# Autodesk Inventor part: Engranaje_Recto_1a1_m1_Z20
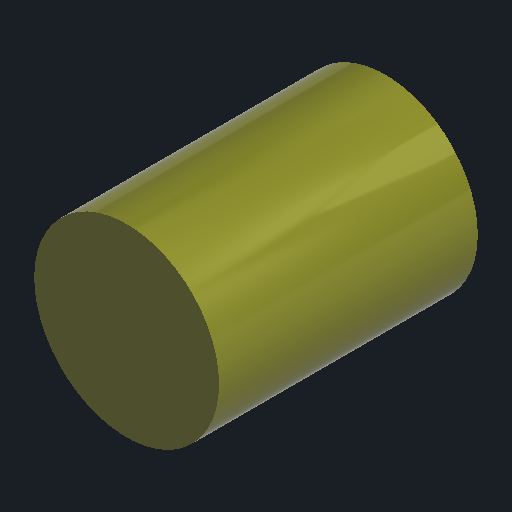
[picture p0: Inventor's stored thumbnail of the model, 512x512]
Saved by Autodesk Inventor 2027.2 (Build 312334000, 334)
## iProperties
Part Number: Engranaje_Recto_1a1_m1_Z20
Material: Genérico
Document SubType Name: Modelado
Designer: Usuario
Appearance: Por defecto
Author: Usuario
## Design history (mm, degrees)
sketch "Boceto1"
  geometry: L1 (8.702, -0.915)-(10.985, -0.576); L2 (10.985, -0.576)-(10.985, 0.576); L3 (10.985, 0.576)-(8.702, 0.915); L4 (8.702, 0.915)-(8.559, 1.819); L5 (8.559, 1.819)-(10.625, 2.847); L6 (10.625, 2.847)-(10.269, 3.942); L7 (10.269, 3.942)-(7.994, 3.559); L8 (7.994, 3.559)-(7.578, 4.375); L9 (7.578, 4.375)-(9.225, 5.991); L10 (9.225, 5.991)-(8.549, 6.923); L11 (8.549, 6.923)-(6.503, 5.855); L12 (6.503, 5.855)-(5.855, 6.503); L13 (5.855, 6.503)-(6.923, 8.549); L14 (6.923, 8.549)-(5.991, 9.225); L15 (5.991, 9.225)-(4.375, 7.578); L16 (4.375, 7.578)-(3.559, 7.994); L17 (3.559, 7.994)-(3.942, 10.269); L18 (3.942, 10.269)-(2.847, 10.625); L19 (2.847, 10.625)-(1.819, 8.559); L20 (1.819, 8.559)-(0.915, 8.702); L21 (0.915, 8.702)-(0.576, 10.985); L22 (0.576, 10.985)-(-0.576, 10.985); L23 (-0.576, 10.985)-(-0.915, 8.702); L24 (-0.915, 8.702)-(-1.819, 8.559); L25 (-1.819, 8.559)-(-2.847, 10.625); L26 (-2.847, 10.625)-(-3.942, 10.269); L27 (-3.942, 10.269)-(-3.559, 7.994); L28 (-3.559, 7.994)-(-4.375, 7.578); L29 (-4.375, 7.578)-(-5.991, 9.225); L30 (-5.991, 9.225)-(-6.923, 8.549); L31 (-6.923, 8.549)-(-5.855, 6.503); L32 (-5.855, 6.503)-(-6.503, 5.855); L33 (-6.503, 5.855)-(-8.549, 6.923); L34 (-8.549, 6.923)-(-9.225, 5.991); L35 (-9.225, 5.991)-(-7.578, 4.375); L36 (-7.578, 4.375)-(-7.994, 3.559); L37 (-7.994, 3.559)-(-10.269, 3.942); L38 (-10.269, 3.942)-(-10.625, 2.847); L39 (-10.625, 2.847)-(-8.559, 1.819); L40 (-8.559, 1.819)-(-8.702, 0.915); L41 (-8.702, 0.915)-(-10.985, 0.576); L42 (-10.985, 0.576)-(-10.985, -0.576); L43 (-10.985, -0.576)-(-8.702, -0.915); L44 (-8.702, -0.915)-(-8.559, -1.819); L45 (-8.559, -1.819)-(-10.625, -2.847); L46 (-10.625, -2.847)-(-10.269, -3.942); L47 (-10.269, -3.942)-(-7.994, -3.559); L48 (-7.994, -3.559)-(-7.578, -4.375); L49 (-7.578, -4.375)-(-9.225, -5.991); L50 (-9.225, -5.991)-(-8.549, -6.923); L51 (-8.549, -6.923)-(-6.503, -5.855); L52 (-6.503, -5.855)-(-5.855, -6.503); L53 (-5.855, -6.503)-(-6.923, -8.549); L54 (-6.923, -8.549)-(-5.991, -9.225); L55 (-5.991, -9.225)-(-4.375, -7.578); L56 (-4.375, -7.578)-(-3.559, -7.994); L57 (-3.559, -7.994)-(-3.942, -10.269); L58 (-3.942, -10.269)-(-2.847, -10.625); L59 (-2.847, -10.625)-(-1.819, -8.559); L60 (-1.819, -8.559)-(-0.915, -8.702); L61 (-0.915, -8.702)-(-0.576, -10.985); L62 (-0.576, -10.985)-(0.576, -10.985); L63 (0.576, -10.985)-(0.915, -8.702); L64 (0.915, -8.702)-(1.819, -8.559)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; C1 r 2.5 at (0, 0)
  constraints: 160 end point, 1 centre point
extrude "Extrusión1" new body sketch "Boceto1" distance "d0" = 7; taper "d1" = 0 deg
node "Sólido1"
node "Cuerpos sólidos"
node "Cuerpos de superficie"
